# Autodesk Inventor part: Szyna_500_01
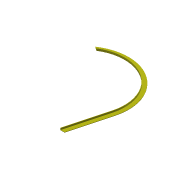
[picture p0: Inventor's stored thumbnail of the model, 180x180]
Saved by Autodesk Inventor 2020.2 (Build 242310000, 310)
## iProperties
Created: 2014-10
Part Number: Szyna_500_01
Material: Ogólny
Document SubType Name: Modeling
Designer: F.Stasiak
Density: 1 g/cm^3
Appearance: Żółta
Catalog Web Link: www.expertbooks.pl
Manager: www.cadconsulting.pl
Company: Fabian Stasiak CAD Consulting
Author: F.Stasiak
Subject: Zbiór ćwiczeń. Autodesk Inventor 2020. Kurs Professional
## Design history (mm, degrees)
sketch "Szkic1"
  geometry: L1 (0, 0)-(258.819, 965.926); L2 (-103.528, 0)-(162.226, 991.808); L3 (0, 0)-(-103.528, 0); L4 (-1331.492, 2100)-(-1419.027, 2162.423); A1 r 1000 centre (-803.699, 1250.627) between (162.226, 991.808) and (-1331.492, 2100); A2 r 1100 centre (-803.699, 1250.627) between (258.819, 965.926) and (-1419.027, 2162.423)
  constraints: 8 end point, 4 point on circle, 2 centre point, 2 tangent, 1 concentric, 1 horizontal, 1 point on line
  dimensions: "d3" = 100 distance between parallel lines of L1 L2; "d18" = 1000 radius of A1; "d19" = 1000 distance of L1.start L1.end; "d20" = 75 deg angle of L1 L3; "d21" = 2100 vertical distance of L4.start L1.start
extrude "Wyciągnięcie proste1" new body sketch "Szkic1" distance "d4" = 50; taper "d5" = 0 deg
feature "Skorupa2" dims "d12" = 10
node "Bryła1"
